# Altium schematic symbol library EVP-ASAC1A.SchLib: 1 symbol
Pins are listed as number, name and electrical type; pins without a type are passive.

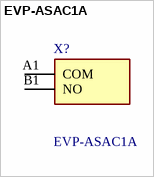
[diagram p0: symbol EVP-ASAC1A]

## EVP-ASAC1A
designator X?
Tactile Switches Swtch Lite Touch SMD 5mm ht J-bent 1.6N; Manufacturer_Name: Panasonic; Geometry.Height: 5.2mm
footprint EVPASAC1A
pins: A1 COM, B1 NO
